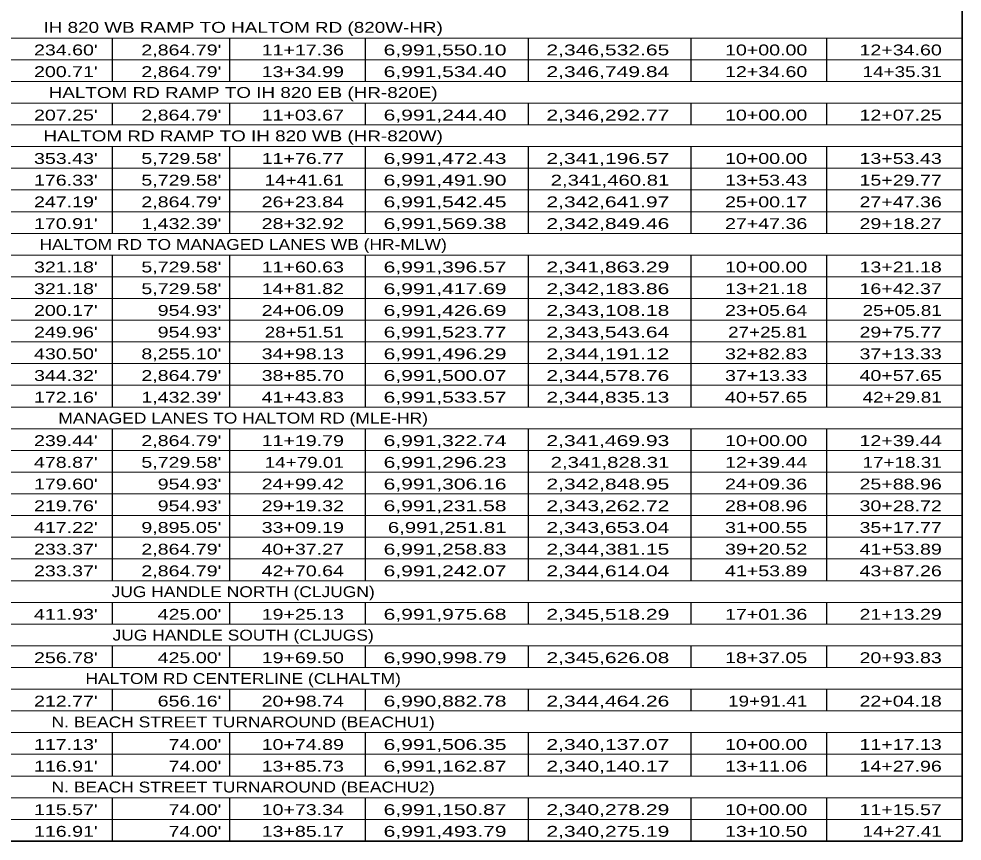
# Model space of a CAD drawing. Extents: x 1953053 to 1967065, y 7363860 to 7371201.
# Drawn here: x 1958608 to 1959651, y 7368424 to 7369333 of the extents above; entities that cross this region are included whole.
import ezdxf
from ezdxf.enums import TextEntityAlignment as Align

# ---------------------------------------------------------------- set-up
doc = ezdxf.new("R2010")
doc.units = 0
doc.header["$LTSCALE"] = 4.8
doc.layers.add('10', color=7, linetype='Continuous')
doc.layers.add('12', color=7, linetype='Continuous', lineweight=25)

msp = doc.modelspace()

# ---------------------------------------------------------------- linework, layer by layer
at = {"layer": '12', "lineweight": 35}
for p, q in [((1959650.637, 7368423.747), (1959650.637, 7370164.879)), ((1957927.305, 7368423.747), (1959650.637, 7368423.747))]:
    msp.add_line(p, q, dxfattribs=at)
at = {"layer": '12', "lineweight": 13}
for p, q in [((1957927.305, 7369311.746), (1959650.637, 7369311.746)), ((1957927.305, 7369287.746), (1959650.637, 7369287.746)), ((1957927.305, 7369263.746), (1959650.637, 7369263.746)), ((1957927.305, 7369239.746), (1959650.637, 7369239.746)), ((1957927.305, 7369215.746), (1959650.637, 7369215.746)), ((1957927.305, 7369191.746), (1959650.637, 7369191.746)), ((1957927.305, 7369167.746), (1959650.637, 7369167.746)), ((1957927.305, 7369143.746), (1959650.637, 7369143.746)), ((1957927.305, 7369119.746), (1959650.637, 7369119.746)), ((1957927.305, 7369095.746), (1959650.637, 7369095.746)), ((1957927.305, 7369071.746), (1959650.637, 7369071.746)), ((1957927.305, 7369047.746), (1959650.637, 7369047.746)), ((1957927.305, 7369023.746), (1959650.637, 7369023.746)), ((1957927.305, 7368999.746), (1959650.637, 7368999.746)), ((1957927.305, 7368975.747), (1959650.637, 7368975.747)), ((1957927.305, 7368951.747), (1959650.637, 7368951.747)), ((1957927.305, 7368927.747), (1959650.637, 7368927.747)), ((1957927.305, 7368903.747), (1959650.637, 7368903.747)), ((1957927.305, 7368879.747), (1959650.637, 7368879.747)), ((1957927.305, 7368855.747), (1959650.637, 7368855.747)), ((1957927.305, 7368831.747), (1959650.637, 7368831.747)), ((1957927.305, 7368807.747), (1959650.637, 7368807.747)), ((1957927.305, 7368783.747), (1959650.637, 7368783.747)), ((1957927.305, 7368759.747), (1959650.637, 7368759.747)), ((1957927.305, 7368735.747), (1959650.637, 7368735.747)), ((1957927.305, 7368711.747), (1959650.637, 7368711.747)), ((1957927.305, 7368687.747), (1959650.637, 7368687.747)), ((1957927.305, 7368663.747), (1959650.637, 7368663.747)), ((1957927.305, 7368663.747), (1959650.637, 7368663.747)), ((1957927.305, 7368639.747), (1959650.637, 7368639.747)), ((1957927.305, 7368615.747), (1959650.637, 7368615.747)), ((1957927.305, 7368591.747), (1959650.637, 7368591.747)), ((1957927.305, 7368567.747), (1959650.637, 7368567.747)), ((1957927.305, 7368567.747), (1959650.637, 7368567.747)), ((1957927.305, 7368543.747), (1959650.637, 7368543.747)), ((1957927.305, 7368519.747), (1959650.637, 7368519.747)), ((1957927.305, 7368495.747), (1959650.637, 7368495.747)), ((1957927.305, 7368471.747), (1959650.637, 7368471.747)), ((1957927.305, 7368447.747), (1959650.637, 7368447.747))]:
    msp.add_line(p, q, dxfattribs=at)
at = {"layer": '12'}
for p, q in [((1958710.637, 7369311.746), (1958710.637, 7369263.746)), ((1958840.637, 7369311.746), (1958840.637, 7369263.746)), ((1958990.637, 7369311.746), (1958990.637, 7369263.746)), ((1959170.637, 7369311.746), (1959170.637, 7369263.746)), ((1959350.637, 7369311.746), (1959350.637, 7369263.746)), ((1959500.637, 7369311.746), (1959500.637, 7369263.746)), ((1958710.637, 7369239.746), (1958710.637, 7369215.746)), ((1958840.637, 7369239.746), (1958840.637, 7369215.746)), ((1958990.637, 7369239.746), (1958990.637, 7369215.746)), ((1959170.637, 7369239.746), (1959170.637, 7369215.746)), ((1959350.637, 7369239.746), (1959350.637, 7369215.746)), ((1959500.637, 7369239.746), (1959500.637, 7369215.746)), ((1958710.637, 7369191.746), (1958710.637, 7369095.746)), ((1958840.637, 7369191.746), (1958840.637, 7369095.746)), ((1958990.637, 7369191.746), (1958990.637, 7369095.746)), ((1959170.637, 7369191.746), (1959170.637, 7369095.746)), ((1959350.637, 7369191.746), (1959350.637, 7369095.746)), ((1959500.637, 7369191.746), (1959500.637, 7369095.746)), ((1958710.637, 7369071.746), (1958710.637, 7368903.747)), ((1958840.637, 7369071.746), (1958840.637, 7368903.747)), ((1958990.637, 7369071.746), (1958990.637, 7368903.747)), ((1959170.637, 7369071.746), (1959170.637, 7368903.747)), ((1959350.637, 7369071.746), (1959350.637, 7368903.747)), ((1959500.637, 7369071.746), (1959500.637, 7368903.747)), ((1958710.637, 7368879.747), (1958710.637, 7368711.747)), ((1958840.637, 7368879.747), (1958840.637, 7368711.747)), ((1958990.637, 7368879.747), (1958990.637, 7368711.747)), ((1959170.637, 7368879.747), (1959170.637, 7368711.747)), ((1959350.637, 7368879.747), (1959350.637, 7368711.747)), ((1959500.637, 7368879.747), (1959500.637, 7368711.747)), ((1958710.637, 7368687.747), (1958710.637, 7368663.747)), ((1958840.637, 7368687.747), (1958840.637, 7368663.747)), ((1958990.637, 7368687.747), (1958990.637, 7368663.747)), ((1959170.637, 7368687.747), (1959170.637, 7368663.747)), ((1959350.637, 7368687.747), (1959350.637, 7368663.747)), ((1959500.637, 7368687.747), (1959500.637, 7368663.747)), ((1958710.637, 7368639.747), (1958710.637, 7368615.747)), ((1958840.637, 7368639.747), (1958840.637, 7368615.747)), ((1958990.637, 7368639.747), (1958990.637, 7368615.747)), ((1959170.637, 7368639.747), (1959170.637, 7368615.747)), ((1959350.637, 7368639.747), (1959350.637, 7368615.747)), ((1959500.637, 7368639.747), (1959500.637, 7368615.747)), ((1958710.637, 7368591.747), (1958710.637, 7368567.747)), ((1958840.637, 7368591.747), (1958840.637, 7368567.747)), ((1958990.637, 7368591.747), (1958990.637, 7368567.747)), ((1959170.637, 7368591.747), (1959170.637, 7368567.747)), ((1959350.637, 7368591.747), (1959350.637, 7368567.747)), ((1959500.637, 7368591.747), (1959500.637, 7368567.747)), ((1958710.637, 7368543.747), (1958710.637, 7368495.747)), ((1958840.637, 7368543.747), (1958840.637, 7368495.747)), ((1958990.637, 7368543.747), (1958990.637, 7368495.747)), ((1959170.637, 7368543.747), (1959170.637, 7368495.747)), ((1959350.637, 7368543.747), (1959350.637, 7368495.747)), ((1959500.637, 7368543.747), (1959500.637, 7368495.747)), ((1958710.637, 7368471.747), (1958710.637, 7368423.747)), ((1958840.637, 7368471.747), (1958840.637, 7368423.747)), ((1958990.637, 7368471.747), (1958990.637, 7368423.747)), ((1959170.637, 7368471.747), (1959170.637, 7368423.747)), ((1959350.637, 7368471.747), (1959350.637, 7368423.747)), ((1959500.637, 7368471.747), (1959500.637, 7368423.747))]:
    msp.add_line(p, q, dxfattribs=at)

# ---------------------------------------------------------------- texts
at = {"layer": '10'}
for s, width, p in [('IH 820 WB RAMP TO HALTOM RD (820W-HR)', 1.3, (1958855.637, 7369317.54)), ('HALTOM RD RAMP TO IH 820 EB (HR-820E)', 1.3, (1958855.637, 7369245.54)), ('HALTOM RD RAMP TO IH 820 WB (HR-820W)', 1.3, (1958855.637, 7369197.54)), ('HALTOM RD TO MANAGED LANES WB (HR-MLW)', 1.2, (1958855.637, 7369077.54)), ('MANAGED LANES TO HALTOM RD (MLE-HR)', 1.2, (1958855.637, 7368885.541)), ('JUG HANDLE NORTH (CLJUGN)', 1.2, (1958855.637, 7368693.541)), ('JUG HANDLE SOUTH (CLJUGS)', 1.2, (1958855.637, 7368645.541)), ('HALTOM RD CENTERLINE (CLHALTM)', 1.2, (1958855.637, 7368597.541)), ('N. BEACH STREET TURNAROUND (BEACHU1)', 1.2, (1958855.637, 7368549.541)), ('N. BEACH STREET TURNAROUND (BEACHU2)', 1.2, (1958855.637, 7368477.541))]:
    msp.add_text(s, height=12, dxfattribs=dict(at, width=width)).set_placement(p, align=Align.CENTER)
for s, width, p in [("234.60'", 1.35, (1958694.761, 7369292.573)), ("2,864.79'", 1.35, (1958831.53, 7369292.573)), ('11+17.36', 1.35, (1958967.074, 7369292.573)), ('6,991,550.10', 1.45, (1959146.839, 7369292.573)), ('2,346,532.65', 1.45, (1959326.839, 7369292.573)), ('10+00.00', 1.35, (1959479.417, 7369292.573)), ('12+34.60', 1.35, (1959628.149, 7369292.573)), ("200.71'", 1.35, (1958694.761, 7369268.573)), ("2,864.79'", 1.35, (1958831.53, 7369268.573)), ('13+34.99', 1.35, (1958967.074, 7369268.573)), ('6,991,534.40', 1.45, (1959146.839, 7369268.573)), ('2,346,749.84', 1.45, (1959326.839, 7369268.573)), ('12+34.60', 1.35, (1959479.417, 7369268.573)), ('14+35.31', 1.3, (1959628.149, 7369268.573)), ("207.25'", 1.35, (1958694.761, 7369220.573)), ("2,864.79'", 1.35, (1958831.53, 7369220.573)), ('11+03.67', 1.35, (1958967.074, 7369220.573)), ('6,991,244.40', 1.45, (1959146.839, 7369220.573)), ('2,346,292.77', 1.45, (1959326.839, 7369220.573)), ('10+00.00', 1.35, (1959479.417, 7369220.573)), ('12+07.25', 1.35, (1959628.149, 7369220.573)), ("353.43'", 1.35, (1958694.761, 7369172.573)), ("5,729.58'", 1.35, (1958831.53, 7369172.573)), ('11+76.77', 1.35, (1958967.074, 7369172.573)), ('6,991,472.43', 1.45, (1959146.839, 7369172.573)), ('2,341,196.57', 1.45, (1959326.839, 7369172.573)), ('10+00.00', 1.35, (1959479.417, 7369172.573)), ('13+53.43', 1.35, (1959628.149, 7369172.573)), ("176.33'", 1.35, (1958694.761, 7369148.573)), ("5,729.58'", 1.35, (1958831.53, 7369148.573)), ('14+41.61', 1.3, (1958967.074, 7369148.573)), ('6,991,491.90', 1.45, (1959146.839, 7369148.573)), ('2,341,460.81', 1.4, (1959326.839, 7369148.573)), ('13+53.43', 1.35, (1959479.417, 7369148.573)), ('15+29.77', 1.35, (1959628.149, 7369148.573)), ("247.19'", 1.35, (1958694.761, 7369124.573)), ("2,864.79'", 1.35, (1958831.53, 7369124.573)), ('26+23.84', 1.35, (1958967.074, 7369124.573)), ('6,991,542.45', 1.45, (1959146.839, 7369124.573)), ('2,342,641.97', 1.45, (1959326.839, 7369124.573)), ('25+00.17', 1.35, (1959479.417, 7369124.573)), ('27+47.36', 1.35, (1959628.149, 7369124.573)), ("170.91'", 1.35, (1958694.761, 7369100.573)), ("1,432.39'", 1.35, (1958831.53, 7369100.573)), ('28+32.92', 1.35, (1958967.074, 7369100.573)), ('6,991,569.38', 1.45, (1959146.839, 7369100.573)), ('2,342,849.46', 1.45, (1959326.839, 7369100.573)), ('27+47.36', 1.35, (1959479.417, 7369100.573)), ('29+18.27', 1.35, (1959628.149, 7369100.573)), ("321.18'", 1.35, (1958694.761, 7369052.573)), ("5,729.58'", 1.35, (1958831.53, 7369052.573)), ('11+60.63', 1.35, (1958967.074, 7369052.573)), ('6,991,396.57', 1.45, (1959146.839, 7369052.573)), ('2,341,863.29', 1.45, (1959326.839, 7369052.573)), ('10+00.00', 1.35, (1959479.417, 7369052.573)), ('13+21.18', 1.35, (1959628.149, 7369052.573)), ("321.18'", 1.35, (1958694.761, 7369028.573)), ("5,729.58'", 1.35, (1958831.53, 7369028.573)), ('14+81.82', 1.35, (1958967.074, 7369028.573)), ('6,991,417.69', 1.45, (1959146.839, 7369028.573)), ('2,342,183.86', 1.45, (1959326.839, 7369028.573)), ('13+21.18', 1.35, (1959479.417, 7369028.573)), ('16+42.37', 1.35, (1959628.149, 7369028.573)), ("200.17'", 1.35, (1958694.761, 7369004.573)), ("954.93'", 1.35, (1958831.53, 7369004.573)), ('24+06.09', 1.35, (1958967.074, 7369004.573)), ('6,991,426.69', 1.45, (1959146.839, 7369004.573)), ('2,343,108.18', 1.45, (1959326.839, 7369004.573)), ('23+05.64', 1.35, (1959479.417, 7369004.573)), ('25+05.81', 1.3, (1959628.149, 7369004.573)), ("249.96'", 1.35, (1958694.761, 7368980.573)), ("954.93'", 1.35, (1958831.53, 7368980.573)), ('28+51.51', 1.3, (1958967.074, 7368980.573)), ('6,991,523.77', 1.45, (1959146.839, 7368980.573)), ('2,343,543.64', 1.45, (1959326.839, 7368980.573)), ('27+25.81', 1.3, (1959479.417, 7368980.573)), ('29+75.77', 1.35, (1959628.149, 7368980.573)), ("430.50'", 1.35, (1958694.761, 7368956.573)), ("8,255.10'", 1.35, (1958831.53, 7368956.573)), ('34+98.13', 1.35, (1958967.074, 7368956.573)), ('6,991,496.29', 1.45, (1959146.839, 7368956.573)), ('2,344,191.12', 1.45, (1959326.839, 7368956.573)), ('32+82.83', 1.35, (1959479.417, 7368956.573)), ('37+13.33', 1.35, (1959628.149, 7368956.573)), ("344.32'", 1.35, (1958694.761, 7368932.573)), ("2,864.79'", 1.35, (1958831.53, 7368932.573)), ('38+85.70', 1.35, (1958967.074, 7368932.573)), ('6,991,500.07', 1.45, (1959146.839, 7368932.573)), ('2,344,578.76', 1.45, (1959326.839, 7368932.573)), ('37+13.33', 1.35, (1959479.417, 7368932.573)), ('40+57.65', 1.35, (1959628.149, 7368932.573)), ("172.16'", 1.35, (1958694.761, 7368908.573)), ("1,432.39'", 1.35, (1958831.53, 7368908.573)), ('41+43.83', 1.35, (1958967.074, 7368908.573)), ('6,991,533.57', 1.45, (1959146.839, 7368908.573)), ('2,344,835.13', 1.45, (1959326.839, 7368908.573)), ('40+57.65', 1.35, (1959479.417, 7368908.573)), ('42+29.81', 1.3, (1959628.149, 7368908.573)), ("239.44'", 1.35, (1958694.761, 7368860.574)), ("2,864.79'", 1.35, (1958831.53, 7368860.574)), ('11+19.79', 1.35, (1958967.074, 7368860.574)), ('6,991,322.74', 1.45, (1959146.839, 7368860.574)), ('2,341,469.93', 1.45, (1959326.839, 7368860.574)), ('10+00.00', 1.35, (1959479.417, 7368860.574)), ('12+39.44', 1.35, (1959628.149, 7368860.574)), ("478.87'", 1.35, (1958694.761, 7368836.574)), ("5,729.58'", 1.35, (1958831.53, 7368836.574)), ('14+79.01', 1.3, (1958967.074, 7368836.574)), ('6,991,296.23', 1.45, (1959146.839, 7368836.574)), ('2,341,828.31', 1.4, (1959326.839, 7368836.574)), ('12+39.44', 1.35, (1959479.417, 7368836.574)), ('17+18.31', 1.3, (1959628.149, 7368836.574)), ("179.60'", 1.35, (1958694.761, 7368812.574)), ("954.93'", 1.35, (1958831.53, 7368812.574)), ('24+99.42', 1.35, (1958967.074, 7368812.574)), ('6,991,306.16', 1.45, (1959146.839, 7368812.574)), ('2,342,848.95', 1.45, (1959326.839, 7368812.574)), ('24+09.36', 1.35, (1959479.417, 7368812.574)), ('25+88.96', 1.35, (1959628.149, 7368812.574)), ("219.76'", 1.35, (1958694.761, 7368788.574)), ("954.93'", 1.35, (1958831.53, 7368788.574)), ('29+19.32', 1.35, (1958967.074, 7368788.574)), ('6,991,231.58', 1.45, (1959146.839, 7368788.574)), ('2,343,262.72', 1.45, (1959326.839, 7368788.574)), ('28+08.96', 1.35, (1959479.417, 7368788.574)), ('30+28.72', 1.35, (1959628.149, 7368788.574)), ("417.22'", 1.35, (1958694.761, 7368764.574)), ("9,895.05'", 1.35, (1958831.53, 7368764.574)), ('33+09.19', 1.35, (1958967.074, 7368764.574)), ('6,991,251.81', 1.4, (1959146.839, 7368764.574)), ('2,343,653.04', 1.45, (1959326.839, 7368764.574)), ('31+00.55', 1.35, (1959479.417, 7368764.574)), ('35+17.77', 1.35, (1959628.149, 7368764.574)), ("233.37'", 1.35, (1958694.761, 7368740.574)), ("2,864.79'", 1.35, (1958831.53, 7368740.574)), ('40+37.27', 1.35, (1958967.074, 7368740.574)), ('6,991,258.83', 1.45, (1959146.839, 7368740.574)), ('2,344,381.15', 1.45, (1959326.839, 7368740.574)), ('39+20.52', 1.35, (1959479.417, 7368740.574)), ('41+53.89', 1.35, (1959628.149, 7368740.574)), ("233.37'", 1.35, (1958694.761, 7368716.574)), ("2,864.79'", 1.35, (1958831.53, 7368716.574)), ('42+70.64', 1.35, (1958967.074, 7368716.574)), ('6,991,242.07', 1.45, (1959146.839, 7368716.574)), ('2,344,614.04', 1.45, (1959326.839, 7368716.574)), ('41+53.89', 1.35, (1959479.417, 7368716.574)), ('43+87.26', 1.35, (1959628.149, 7368716.574)), ("411.93'", 1.35, (1958694.761, 7368668.574)), ("425.00'", 1.35, (1958831.53, 7368668.574)), ('19+25.13', 1.35, (1958967.074, 7368668.574)), ('6,991,975.68', 1.45, (1959146.839, 7368668.574)), ('2,345,518.29', 1.45, (1959326.839, 7368668.574)), ('17+01.36', 1.35, (1959479.417, 7368668.574)), ('21+13.29', 1.35, (1959628.149, 7368668.574)), ("256.78'", 1.35, (1958694.761, 7368620.574)), ("425.00'", 1.35, (1958831.53, 7368620.574)), ('19+69.50', 1.35, (1958967.074, 7368620.574)), ('6,990,998.79', 1.45, (1959146.839, 7368620.574)), ('2,345,626.08', 1.45, (1959326.839, 7368620.574)), ('18+37.05', 1.35, (1959479.417, 7368620.574)), ('20+93.83', 1.35, (1959628.149, 7368620.574)), ("212.77'", 1.35, (1958694.761, 7368572.574)), ("656.16'", 1.35, (1958831.53, 7368572.574)), ('20+98.74', 1.35, (1958967.074, 7368572.574)), ('6,990,882.78', 1.45, (1959146.839, 7368572.574)), ('2,344,464.26', 1.45, (1959326.839, 7368572.574)), ('19+91.41', 1.3, (1959479.417, 7368572.574)), ('22+04.18', 1.35, (1959628.149, 7368572.574)), ("117.13'", 1.35, (1958694.761, 7368524.574)), ("74.00'", 1.35, (1958831.53, 7368524.574)), ('10+74.89', 1.35, (1958967.074, 7368524.574)), ('6,991,506.35', 1.45, (1959146.839, 7368524.574)), ('2,340,137.07', 1.45, (1959326.839, 7368524.574)), ('10+00.00', 1.35, (1959479.417, 7368524.574)), ('11+17.13', 1.35, (1959628.149, 7368524.574)), ("116.91'", 1.35, (1958694.761, 7368500.574)), ("74.00'", 1.35, (1958831.53, 7368500.574)), ('13+85.73', 1.35, (1958967.074, 7368500.574)), ('6,991,162.87', 1.45, (1959146.839, 7368500.574)), ('2,340,140.17', 1.45, (1959326.839, 7368500.574)), ('13+11.06', 1.35, (1959479.417, 7368500.574)), ('14+27.96', 1.35, (1959628.149, 7368500.574)), ("115.57'", 1.35, (1958694.761, 7368452.574)), ("74.00'", 1.35, (1958831.53, 7368452.574)), ('10+73.34', 1.35, (1958967.074, 7368452.574)), ('6,991,150.87', 1.45, (1959146.839, 7368452.574)), ('2,340,278.29', 1.45, (1959326.839, 7368452.574)), ('10+00.00', 1.35, (1959479.417, 7368452.574)), ('11+15.57', 1.35, (1959628.149, 7368452.574)), ("116.91'", 1.35, (1958694.761, 7368428.574)), ("74.00'", 1.35, (1958831.53, 7368428.574)), ('13+85.17', 1.35, (1958967.074, 7368428.574)), ('6,991,493.79', 1.45, (1959146.839, 7368428.574)), ('2,340,275.19', 1.45, (1959326.839, 7368428.574)), ('13+10.50', 1.35, (1959479.417, 7368428.574)), ('14+27.41', 1.3, (1959628.149, 7368428.574))]:
    msp.add_text(s, height=12, dxfattribs=dict(at, width=width)).set_placement(p, align=Align.RIGHT)

doc.saveas('drawing.dxf')
